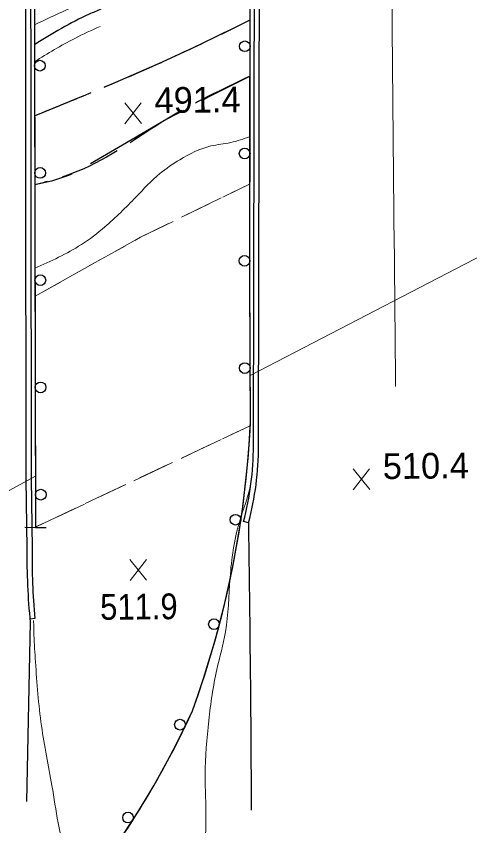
# Model space of a CAD drawing. Extents: x 2362213 to 2366494, y 6968794 to 6978110.
# Drawn here: x 2364395.9 to 2364480.5, y 6970208.3 to 6970359.3 of the extents above; entities that cross this region are included whole.
import ezdxf

# ---------------------------------------------------------------- set-up
doc = ezdxf.new("R2010")
doc.units = 0
doc.header["$LTSCALE"] = 1.9
doc.linetypes.add('LONG_DASHED', pattern=[7.5, 6, -1.5])
doc.linetypes.add('MEDIUM_DASHED', pattern=[4.5, 3, -1.5])
for name, color, linetype, lineweight in [('2', 7, 'Continuous', 25), ('3', 7, 'Continuous', 25), ('31', 7, 'Continuous', 25), ('35', 7, 'Continuous', 13), ('4', 7, 'Continuous', 25), ('62', 7, 'Continuous', 13), ('8', 7, 'Continuous', 13), ('9', 7, 'Continuous', 13)]:
    doc.layers.add(name, color=color, linetype=linetype, lineweight=lineweight)

msp = doc.modelspace()

# ---------------------------------------------------------------- linework, layer by layer
at = {"layer": '2'}
for p, q in [((2364439.191, 6970264.758), (2364438.268, 6970265.009)), ((2364398.481, 6970246.24), (2364397.796, 6970212.841)), ((2364399.346, 6970246.962), (2364398.398, 6970246.823))]:
    msp.add_line(p, q, dxfattribs=at)
for points in [[(2364440.123, 6970279.179), (2364440.489, 6970460.26), (2364440.223, 6970785.244), (2364439.567, 6970959.146)], [(2364441.083, 6970279.178), (2364441.449, 6970460.26), (2364441.183, 6970785.243), (2364440.527, 6970959.145)], [(2364396.955, 6970944.499), (2364397.691, 6970272.954), (2364397.874, 6970259.995)], [(2364397.914, 6970944.452), (2364398.65, 6970272.964), (2364398.833, 6970260.03)]]:
    msp.add_lwpolyline(points, dxfattribs=at)
for centre, radius, start, end in [((2364385.48, 6970279.143), 54.643, 345.00743, 0.03555), ((2364385.48, 6970279.143), 55.603, 345.00743, 0.03555), ((2364520.826, 6970258.534), 122.961, 179.31895, 185.73812), ((2364515.609, 6970258.071), 116.792, 179.03873, 185.45791)]:
    msp.add_arc(centre, radius, start, end, dxfattribs=at)
msp.add_spline([(2364439.191, 6970264.758), (2364439.606, 6970227.421), (2364439.705, 6970211.22)], degree=3, dxfattribs=at)
at = {"layer": '3'}
msp.add_line((2364434.132, 6970355.906), (2364439.537, 6970358.567), dxfattribs=at)
for points in [[(2364412.245, 6970346.056), (2364415.313, 6970347.346), (2364423.16, 6970350.76), (2364430.529, 6970354.161)], [(2364439.517, 6970348.096), (2364431.694, 6970344.141), (2364430.6, 6970343.561)], [(2364399.305, 6970340.703), (2364403.369, 6970342.352), (2364407.433, 6970344.03), (2364408.56, 6970344.501)], [(2364427.056, 6970341.697), (2364423.942, 6970340.047), (2364415.699, 6970335.209), (2364409.732, 6970331.722)], [(2364406.219, 6970329.818), (2364405.452, 6970329.471), (2364402.431, 6970328.512), (2364399.337, 6970327.793)]]:
    msp.add_lwpolyline(points, dxfattribs=at)
at = {"layer": '3', "linetype": 'LONG_DASHED'}
for points in [[(2364399.305, 6970340.703), (2364407.433, 6970344.03), (2364423.16, 6970350.76), (2364439.537, 6970358.567)], [(2364439.517, 6970348.096), (2364423.942, 6970340.047), (2364407.384, 6970330.349), (2364399.337, 6970327.793)]]:
    msp.add_spline(points, degree=3, dxfattribs=at)
at = {"layer": '31', "lineweight": 13}
for p, q in [((2364419.24, 6970339.243), (2364416.124, 6970343.093)), ((2364416.161, 6970339.213), (2364419.203, 6970343.122)), ((2364461.822, 6970270.985), (2364458.705, 6970274.835)), ((2364458.742, 6970270.956), (2364461.785, 6970274.865)), ((2364420.181, 6970254.078), (2364417.065, 6970257.928)), ((2364417.102, 6970254.048), (2364420.144, 6970257.958))]:
    msp.add_line(p, q, dxfattribs=at)
at = {"layer": '31'}
msp.add_spline([(2364411.657, 6970360.551), (2364409.476, 6970359.631), (2364399.278, 6970353.953)], degree=3, dxfattribs=at)
at = {"layer": '35'}
for points in [[(2364409.54, 6970362.321), (2364405.257, 6970360.44), (2364399.273, 6970357.663)], [(2364411.508, 6970357.34), (2364406.778, 6970355.126), (2364399.288, 6970350.793)], [(2364439.504, 6970336.835), (2364435.875, 6970335.701), (2364432.161, 6970335.065), (2364426.394, 6970332.511), (2364422.688, 6970329.925), (2364418.181, 6970325.522), (2364412.414, 6970319.977), (2364408.024, 6970316.675), (2364399.365, 6970312.262)], [(2364439.873, 6970273.926), (2364439.573, 6970271.853), (2364437.489, 6970264.922), (2364435.768, 6970254.536), (2364434.904, 6970244.437), (2364433.3, 6970237.462), (2364431.781, 6970227.907), (2364431.118, 6970217.759), (2364431.255, 6970209.671), (2364430.825, 6970198.096), (2364430.844, 6970189.806), (2364430.881, 6970181.656), (2364431.01, 6970172.396), (2364432.277, 6970156.888), (2364432.095, 6970146.626), (2364431.735, 6970134.002), (2364432.403, 6970112.178)], [(2364399.111, 6970246.587), (2364399.187, 6970243.826), (2364399.465, 6970238.84), (2364400.588, 6970226.93), (2364402.534, 6970215.788), (2364403.681, 6970208.819), (2364405.24, 6970201.523), (2364406.682, 6970193.955), (2364407.51, 6970183.654), (2364407.687, 6970173.544), (2364407.192, 6970161.45), (2364407.438, 6970151.311), (2364408.118, 6970141.918), (2364408.317, 6970131.498), (2364408.055, 6970113.816), (2364407.983, 6970111.975)]]:
    msp.add_spline(points, degree=3, dxfattribs=at)
at = {"layer": '4'}
for points in [[(2364398.117, 6970940.04), (2364398.351, 6970848.338), (2364398.554, 6970756.636), (2364398.762, 6970632.932), (2364398.96, 6970509.227), (2364399.198, 6970386.554), (2364399.466, 6970263.88)], [(2364439.571, 6970283.654), (2364439.507, 6970296.664), (2364439.463, 6970309.674), (2364439.498, 6970346.966), (2364439.573, 6970384.248), (2364439.548, 6970445.632), (2364439.414, 6970507.022), (2364439.299, 6970532.673), (2364439.165, 6970558.333)], [(2364415.34, 6970205.859), (2364416.957, 6970208.325), (2364418.563, 6970210.83), (2364420.099, 6970213.355), (2364421.595, 6970215.889), (2364423.06, 6970218.473), (2364424.465, 6970221.066), (2364425.82, 6970223.69), (2364427.145, 6970226.353), (2364428.409, 6970229.015), (2364428.743, 6970229.718), (2364429.824, 6970232.729), (2364430.826, 6970235.748), (2364431.768, 6970238.777), (2364432.698, 6970241.845), (2364433.539, 6970244.914), (2364434.33, 6970247.992), (2364435.09, 6970251.1), (2364435.781, 6970254.206), (2364436.411, 6970257.322), (2364436.991, 6970260.468), (2364437.511, 6970263.602), (2364438.001, 6970266.758), (2364438.411, 6970269.922), (2364438.761, 6970273.085), (2364439.071, 6970276.259), (2364439.331, 6970279.421), (2364439.52, 6970282.623), (2364439.571, 6970283.654)], [(2364401.466, 6970263.869), (2364399.466, 6970263.88), (2364397.467, 6970263.891)]]:
    msp.add_lwpolyline(points, dxfattribs=at)
for centre in [(2364438.514, 6970353.655), (2364400.281, 6970350.042), (2364438.488, 6970333.655), (2364400.324, 6970330.042), (2364438.467, 6970313.654), (2364400.367, 6970310.042), (2364438.52, 6970293.648), (2364400.41, 6970290.042), (2364400.453, 6970270.042), (2364436.771, 6970265.372), (2364432.758, 6970245.89), (2364426.424, 6970227.155), (2364416.73, 6970209.822)]:
    msp.add_circle(centre, 1, dxfattribs=at)
for centre, radius, start, end in [((2364257.158, 6970292.216), 182.613, 339.98642, 357.31249), ((2364274.816, 6970300.538), 169.437, 324.02993, 335.29347)]:
    msp.add_arc(centre, radius, start, end, dxfattribs=at)
for points in [[(2364398.117, 6970940.04), (2364398.554, 6970756.636), (2364398.96, 6970509.227), (2364399.466, 6970263.88)], [(2364439.571, 6970283.654), (2364439.463, 6970309.674), (2364439.573, 6970384.248), (2364439.414, 6970507.022), (2364439.165, 6970558.333)]]:
    msp.add_spline(points, degree=3, dxfattribs=at)
at = {"layer": '62'}
msp.add_spline([(2364465.159, 6970688.167), (2364465.393, 6970558.563), (2364465.707, 6970399.709), (2364466.639, 6970290.242)], degree=3, dxfattribs=at)
at = {"layer": '8'}
for p, q in [((2364439.518, 6970328.025), (2364435.925, 6970326.271)), ((2364434.123, 6970325.394), (2364426.935, 6970321.885)), ((2364416.227, 6970316.473), (2364409.244, 6970312.566)), ((2364407.492, 6970311.589), (2364400.509, 6970307.683)), ((2364439.508, 6970282.903), (2364435.894, 6970281.199)), ((2364434.082, 6970280.341), (2364426.853, 6970276.922)), ((2364425.041, 6970276.065), (2364417.804, 6970272.646)), ((2364415.993, 6970271.789), (2364408.755, 6970268.37)), ((2364406.942, 6970267.512), (2364399.704, 6970264.092))]:
    msp.add_line(p, q, dxfattribs=at)
at = {"layer": '8', "linetype": 'MEDIUM_DASHED'}
msp.add_line((2364439.508, 6970282.903), (2364399.684, 6970264.082), dxfattribs=at)
msp.add_lwpolyline([(2364439.518, 6970328.025), (2364419.032, 6970318.04), (2364399.375, 6970307.052)], dxfattribs=at)
at = {"layer": '8'}
msp.add_lwpolyline([(2364425.133, 6970321.008), (2364419.032, 6970318.04), (2364417.968, 6970317.45)], dxfattribs=at)
at = {"layer": '9'}
for p, q in [((2364482.936, 6970314.778), (2364439.538, 6970292.284)), ((2364399.444, 6970273.501), (2364365.102, 6970254.803))]:
    msp.add_line(p, q, dxfattribs=at)

# ---------------------------------------------------------------- texts
at = {"layer": '31'}
for s, p in [('491.4', (2364421.681, 6970341.206)), ('510.4', (2364464.264, 6970272.948))]:
    msp.add_text(s, height=4.8, rotation=0.546, dxfattribs=at).set_placement(p)
at = {"layer": '31', "width": 0.9}
msp.add_text('511.9', height=4.8, rotation=0.546, dxfattribs=at).set_placement((2364411.551, 6970246.695))

doc.saveas('drawing.dxf')
